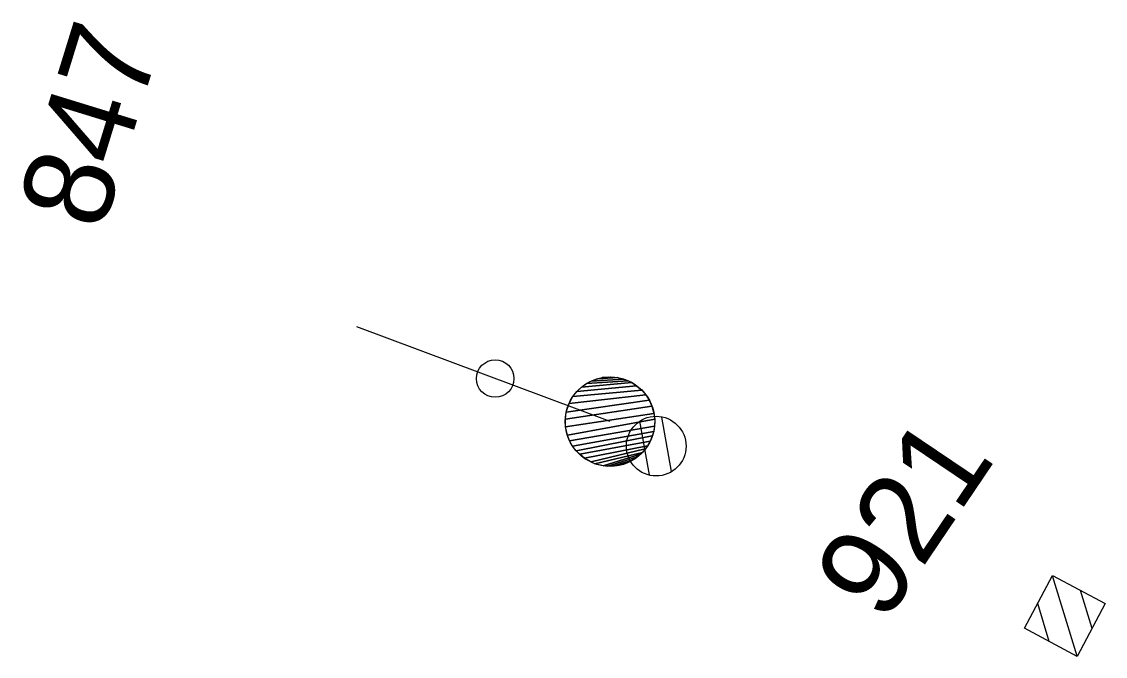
# Model space of a CAD drawing. Extents: x -595867 to -593796, y -1159595 to -1157495.
# Drawn here: x -594750.81 to -594732.66, y -1157963.02 to -1157952.39 of the extents above; entities that cross this region are included whole.
import ezdxf

# ---------------------------------------------------------------- set-up
doc = ezdxf.new("R2010")
doc.units = 0
doc.layers.add('BVK_kanalizace_destova_nova', color=7, linetype='Continuous')
doc.layers.add('BVK_kanalizace_jednotna_nova', color=7, linetype='Continuous')

# ---------------------------------------------------------------- blocks, each defined once
blk = doc.blocks.new('st_tecka')
blk.add_circle((0, 0), 0.00314)
blk = doc.blocks.new('st_1t')
for points in [[(-0.00711, 0.00221), (0.00057, 0.00744), (0.00185, 0.00722), (-0.00729, 0.00159)], [(-0.00689, 0.00294), (-0.00011, 0.00749), (0.00057, 0.00744), (-0.00711, 0.00221)], [(-0.00669, 0.00331), (-0.00149, 0.00733), (-0.00011, 0.00749), (-0.00689, 0.00294)], [(-0.00627, 0.00403), (-0.00222, 0.00714), (-0.00149, 0.00733), (-0.00669, 0.00331)], [(-0.00742, 0.00071), (0.00284, 0.0069), (0.00359, 0.00656), (-0.00747, -0.00023)], [(-0.00747, -0.00023), (0.00359, 0.00656), (0.00442, 0.00605), (-0.00743, -0.00101)], [(-0.00743, -0.00101), (0.00442, 0.00605), (0.00522, 0.0054), (-0.00722, -0.0019)], [(-0.00729, 0.00159), (0.00185, 0.00722), (0.00284, 0.0069), (-0.00742, 0.00071)], [(-0.00579, 0.00472), (-0.00315, 0.00675), (-0.00222, 0.00714), (-0.00627, 0.00403)], [(-0.00526, 0.00533), (-0.00413, 0.00624), (-0.00315, 0.00675), (-0.00579, 0.00472)], [(-0.00722, -0.0019), (0.00522, 0.0054), (0.00588, 0.00461), (-0.00688, -0.00302)], [(-0.00688, -0.00302), (0.00588, 0.00461), (0.00666, 0.00341), (-0.00639, -0.00386)], [(-0.00639, -0.00386), (0.00666, 0.00341), (0.00712, 0.00224), (-0.00567, -0.00488)], [(-0.00567, -0.00488), (0.00712, 0.00224), (0.00742, 0.00112), (-0.00488, -0.00564)], [(-0.00488, -0.00564), (0.00742, 0.00112), (0.00748, -0.00042), (-0.00405, -0.00629)], [(-0.00405, -0.00629), (0.00748, -0.00042), (0.00729, -0.00175), (-0.00317, -0.00679)], [(-0.00317, -0.00679), (0.00729, -0.00175), (0.00698, -0.00275), (-0.00206, -0.00718)], [(-0.00206, -0.00718), (0.00698, -0.00275), (0.00651, -0.0037), (-0.00114, -0.0074)], [(-0.00114, -0.0074), (0.00651, -0.0037), (0.00592, -0.00458), (-0.00048, -0.00747)], [(-0.00048, -0.00747), (0.00592, -0.00458), (0.00536, -0.00524), (0.00037, -0.00747)], [(0.00037, -0.00747), (0.00536, -0.00524), (0.00449, -0.00597), (0.00138, -0.00739)], [(0.00138, -0.00739), (0.00449, -0.00597), (0.00384, -0.00644), (0.0025, -0.00702)], [(0.0025, -0.00702), (0.00384, -0.00644), (0.00295, -0.00692), (0.00293, -0.00693)]]:
    blk.add_lwpolyline(points, close=True)
blk.add_circle((0, 0), 0.0075)
blk = doc.blocks.new('st1k_1t')
blk.add_line((0, 0), (0.04531, 0))
blk.add_blockref('st_1t', (0, 0))
at = {"rotation": 90}
blk.add_blockref('st_tecka', (0.02054, 0), dxfattribs=at)

msp = doc.modelspace()

# ---------------------------------------------------------------- linework, layer by layer
at = {"layer": 'BVK_kanalizace_jednotna_nova'}
for p, q in [((-594739.923, -1157959.925), (-594740.085, -1157959.013)), ((-594740.293, -1157959.983), (-594740.453, -1157959.084)), ((-594733.131, -1157963.021), (-594733.542, -1157961.673)), ((-594732.881, -1157962.558), (-594733.075, -1157961.918)), ((-594733.599, -1157962.772), (-594733.791, -1157962.14))]:
    msp.add_line(p, q, dxfattribs=at)
msp.add_lwpolyline([(-594734.011, -1157962.552), (-594733.54, -1157961.67), (-594732.658, -1157962.14), (-594733.129, -1157963.023)], close=True, dxfattribs=at)
msp.add_lwpolyline([(-594734.011, -1157962.552), (-594733.54, -1157961.67), (-594732.658, -1157962.14), (-594733.129, -1157963.023), (-594734.011, -1157962.552)], dxfattribs=at)
msp.add_circle((-594740.18, -1157959.5), 0.5, dxfattribs=at)
msp.add_circle((-594740.18, -1157959.5), 0.5, dxfattribs=at)

# ---------------------------------------------------------------- block references
at = {"layer": 'BVK_kanalizace_destova_nova', "xscale": 100, "yscale": 100, "rotation": 159.45183390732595}
msp.add_blockref('st1k_1t', (-594740.953, -1157959.089), dxfattribs=at)

# ---------------------------------------------------------------- texts
at = {"layer": 'BVK_kanalizace_jednotna_nova'}
for s, rotation, p in [('847', 72.8965, (-594749.456, -1157955.93)), ('921', 56, (-594736.359, -1157962.492))]:
    msp.add_text(s, height=1.5, rotation=rotation, dxfattribs=at).set_placement(p)

doc.saveas('drawing.dxf')
